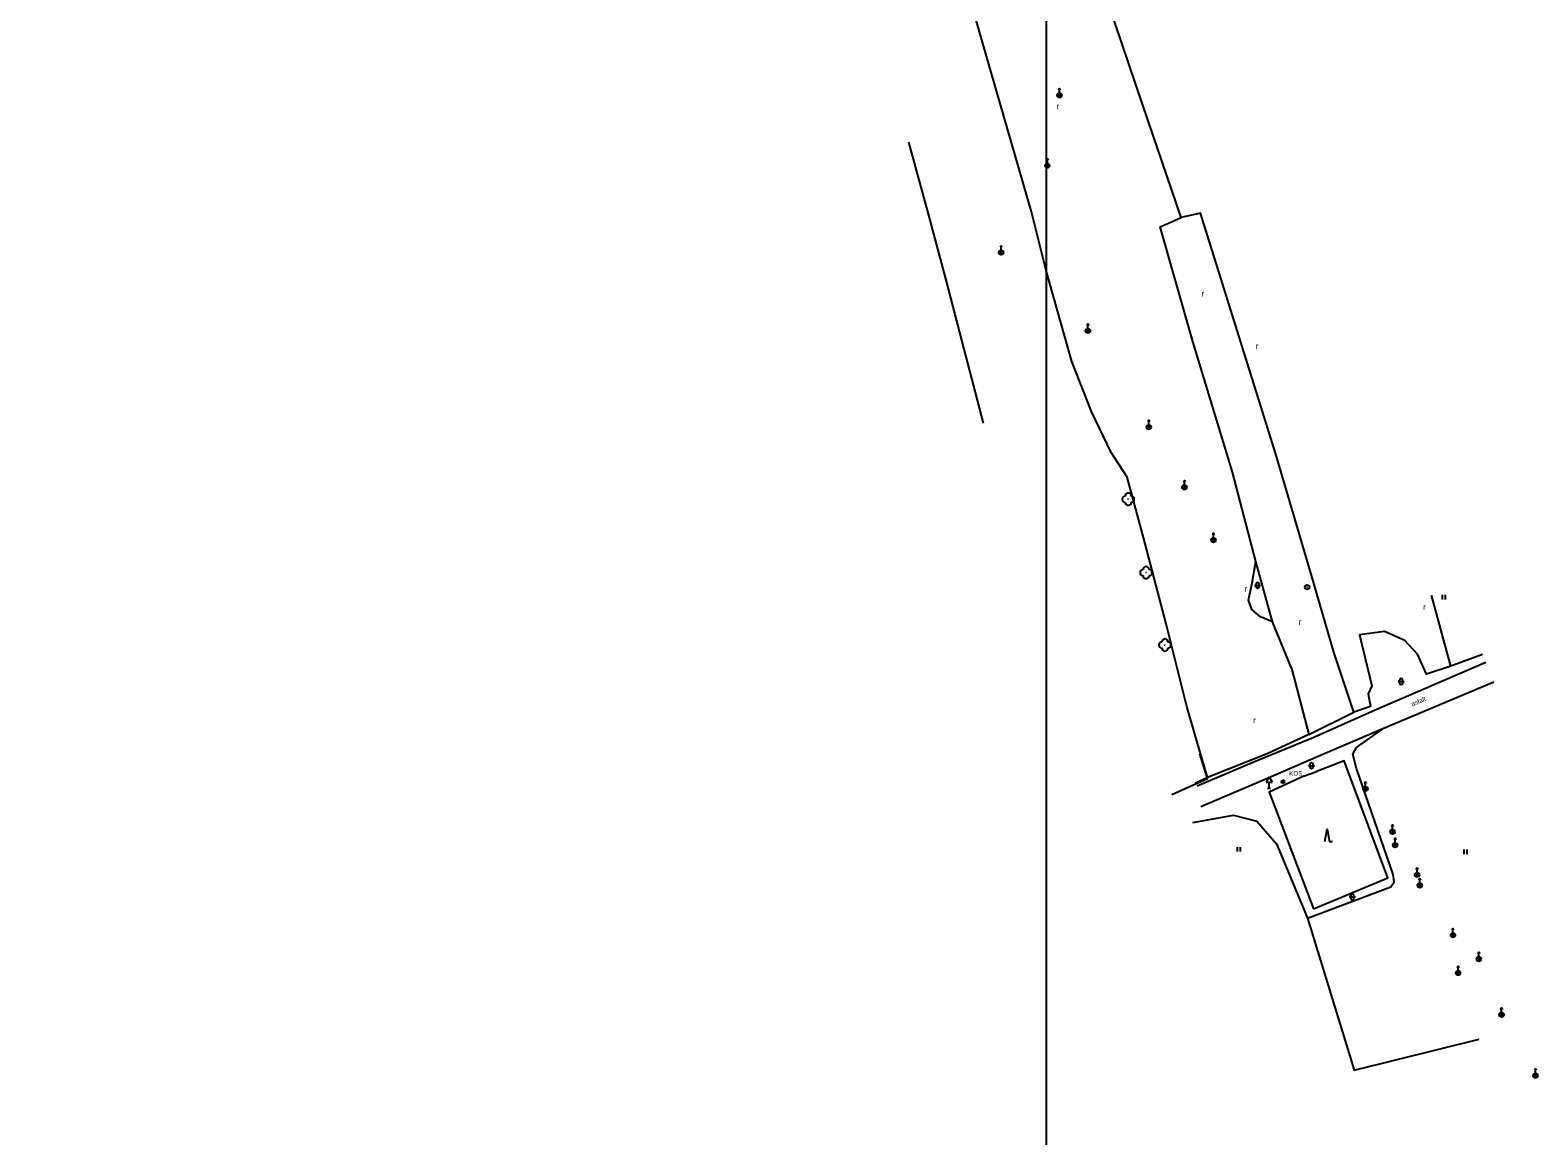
# Model space of a CAD drawing. Extents: x -582188 to -561562, y -1187250 to -1183500.
# Drawn here: x -575479.1 to -575231.9, y -1183947 to -1183765.7 of the extents above; entities that cross this region are included whole.
import ezdxf

# ---------------------------------------------------------------- set-up
doc = ezdxf.new("R2010")
doc.units = 0
for name, color, linetype in [('MAP_ZN_BP', 7, 'Continuous'), ('POMOC_POPIS', 7, 'Continuous'), ('ROZHRANÍ_PLOCH', 7, 'Continuous'), ('RÁMY_ML', 7, 'Continuous'), ('ZELEŇ', 7, 'Continuous'), ('ZN_BP', 7, 'Continuous'), ('ZN_DOPLŇKOVÉ', 7, 'Continuous'), ('ZN_KULTUR', 7, 'Continuous')]:
    doc.layers.add(name, color=color, linetype=linetype)

msp = doc.modelspace()

# ---------------------------------------------------------------- linework, layer by layer
at = {"layer": 'MAP_ZN_BP'}
for radius in [0.375, 0.0005]:
    msp.add_circle((-575269.75, -1183856.991), radius, dxfattribs=at)
at = {"layer": 'ROZHRANÍ_PLOCH'}
for points in [[(-575240.45, -1183869.34), (-575258.62, -1183877.16), (-575268.65, -1183881.64), (-575278.76, -1183885.82), (-575287.77, -1183889.63)], [(-575239.12, -1183872.56), (-575257.33, -1183880.22), (-575267.93, -1183884.77), (-575276.92, -1183888.62), (-575287.2, -1183893.03)]]:
    msp.add_lwpolyline(points, dxfattribs=at)
at = {"layer": 'RÁMY_ML'}
msp.add_lwpolyline([(-575625, -1184000), (-575312.5, -1184000), (-575312.5, -1183750)], dxfattribs=at)
at = {"layer": 'ZELEŇ'}
for p, q in [((-575269.48, -1183881.13), (-575262.11, -1183877.47)), ((-575286.07, -1183888.19), (-575288.09, -1183889.16))]:
    msp.add_line(p, q, dxfattribs=at)
for points in [[(-575272.31, -1183870.28), (-575275.45, -1183862.67), (-575278.15, -1183852.81), (-575281.97, -1183838.13), (-575288.5, -1183816.7), (-575293.86, -1183797.92), (-575290.42, -1183796.4), (-575296.7, -1183777.96), (-575301.3, -1183764.43), (-575306.69, -1183747.6), (-575310.14, -1183736.48), (-575316.18, -1183717.89), (-575322.17, -1183699.18), (-575332.15, -1183671.46)], [(-575272.31, -1183870.28), (-575269.48, -1183881.13), (-575276.3, -1183884.31), (-575286.07, -1183888.19), (-575289.47, -1183876.56), (-575292.87, -1183862.99), (-575296.61, -1183848.85), (-575299.24, -1183838.98), (-575301.89, -1183834.9), (-575305.14, -1183828.2), (-575308.34, -1183820), (-575312.52, -1183805.06), (-575314.93, -1183795.43), (-575320.82, -1183775.21), (-575324.61, -1183761.94), (-575327.94, -1183750.31), (-575319.54, -1183748.15), (-575321.88, -1183739.85), (-575337.2, -1183686.33)], [(-575322.8, -1183830.13), (-575326.4, -1183816.52), (-575328.86, -1183807.03), (-575331.76, -1183796.03), (-575335.07, -1183784.01)], [(-575241, -1183868.05), (-575246.17, -1183869.97), (-575250.2, -1183871.26), (-575251.68, -1183867.97), (-575253.76, -1183865.76), (-575257.08, -1183864.29), (-575261.16, -1183864.83), (-575259.14, -1183873.17), (-575259.76, -1183874.5), (-575259.37, -1183876.55), (-575262.11, -1183877.47), (-575265.36, -1183867.65), (-575269.11, -1183854.88), (-575274.88, -1183835.2), (-575287.26, -1183795.66), (-575290.42, -1183796.4)], [(-575275.45, -1183862.67), (-575277.4, -1183861.88), (-575278.83, -1183860.68), (-575279.36, -1183859.1), (-575278.78, -1183856.28), (-575278.15, -1183852.81)], [(-575246.17, -1183869.97), (-575249.36, -1183858.32)], [(-575261.66, -1183883.28), (-575257.33, -1183880.22)], [(-575291.96, -1183891), (-575286.1, -1183888.34), (-575287.34, -1183884.34)], [(-575269.7, -1183911.24), (-575256.04, -1183906.13), (-575255.49, -1183905.31), (-575255.67, -1183904.1), (-575261.64, -1183886.71), (-575262.27, -1183884.39), (-575261.66, -1183883.28)], [(-575288.49, -1183895.57), (-575281.85, -1183894.35), (-575278.01, -1183895.36), (-575274.79, -1183899.07), (-575269.7, -1183911.24), (-575262.04, -1183936.16), (-575241.55, -1183931.08)]]:
    msp.add_lwpolyline(points, dxfattribs=at)
for centre in [(-575299.09, -1183842.57), (-575296.16, -1183854.6), (-575293.08, -1183866.49)]:
    msp.add_circle(centre, 0.0005, dxfattribs=at)
for centre, start, end in [((-575299.59, -1183842.57), 89.99999, 269.99999), ((-575299.09, -1183842.07), 0, 179.99999), ((-575298.59, -1183842.57), 270, 89.99999), ((-575299.09, -1183843.07), 179.99999, 359.99999), ((-575296.66, -1183854.6), 89.99999, 269.99999), ((-575296.16, -1183854.1), 0, 179.99999), ((-575295.66, -1183854.6), 270, 89.99999), ((-575296.16, -1183855.1), 179.99999, 359.99999), ((-575293.58, -1183866.49), 89.99999, 269.99999), ((-575293.08, -1183865.99), 0, 179.99999), ((-575293.08, -1183866.99), 179.99999, 359.99999), ((-575292.58, -1183866.49), 270, 89.99999)]:
    msp.add_arc(centre, 0.5, start, end, dxfattribs=at)
at = {"layer": 'ZN_BP'}
for p, q in [((-575310.37, -1183775.985), (-575310.37, -1183775.235)), ((-575310.635, -1183776.624), (-575310.106, -1183776.096)), ((-575310.106, -1183776.628), (-575310.635, -1183776.096)), ((-575312.615, -1183788.144), (-575312.086, -1183787.616)), ((-575312.086, -1183788.148), (-575312.615, -1183787.616)), ((-575312.35, -1183787.505), (-575312.35, -1183786.755)), ((-575320.195, -1183802.394), (-575319.666, -1183801.866)), ((-575319.666, -1183802.398), (-575320.195, -1183801.866)), ((-575319.93, -1183801.755), (-575319.93, -1183801.005)), ((-575305.965, -1183815.224), (-575305.436, -1183814.696)), ((-575305.436, -1183815.228), (-575305.965, -1183814.696)), ((-575305.7, -1183814.585), (-575305.7, -1183813.835)), ((-575295.71, -1183830.385), (-575295.71, -1183829.635)), ((-575295.975, -1183831.024), (-575295.446, -1183830.496)), ((-575295.446, -1183831.028), (-575295.975, -1183830.496)), ((-575289.88, -1183840.235), (-575289.88, -1183839.485)), ((-575290.145, -1183840.874), (-575289.616, -1183840.346)), ((-575289.616, -1183840.878), (-575290.145, -1183840.346)), ((-575285.375, -1183849.534), (-575284.846, -1183849.006)), ((-575284.846, -1183849.538), (-575285.375, -1183849.006)), ((-575285.11, -1183848.895), (-575285.11, -1183848.145)), ((-575260.2, -1183889.675), (-575260.2, -1183888.925)), ((-575260.465, -1183890.314), (-575259.936, -1183889.786)), ((-575259.936, -1183890.318), (-575260.465, -1183889.786)), ((-575256.025, -1183897.354), (-575255.496, -1183896.826)), ((-575255.496, -1183897.358), (-575256.025, -1183896.826)), ((-575255.76, -1183896.715), (-575255.76, -1183895.965)), ((-575255.595, -1183899.554), (-575255.066, -1183899.026)), ((-575255.066, -1183899.558), (-575255.595, -1183899.026)), ((-575255.33, -1183898.915), (-575255.33, -1183898.165)), ((-575251.995, -1183904.414), (-575251.466, -1183903.886)), ((-575251.466, -1183904.418), (-575251.995, -1183903.886)), ((-575251.73, -1183903.775), (-575251.73, -1183903.025)), ((-575251.545, -1183906.154), (-575251.016, -1183905.626)), ((-575251.016, -1183906.158), (-575251.545, -1183905.626)), ((-575251.28, -1183905.515), (-575251.28, -1183904.765)), ((-575246.105, -1183914.324), (-575245.576, -1183913.796)), ((-575245.576, -1183914.328), (-575246.105, -1183913.796)), ((-575245.84, -1183913.685), (-575245.84, -1183912.935)), ((-575245, -1183919.885), (-575245, -1183919.135)), ((-575241.875, -1183918.234), (-575241.346, -1183917.706)), ((-575241.346, -1183918.238), (-575241.875, -1183917.706)), ((-575241.61, -1183917.595), (-575241.61, -1183916.845)), ((-575245.265, -1183920.524), (-575244.736, -1183919.996)), ((-575244.736, -1183920.528), (-575245.265, -1183919.996)), ((-575237.87, -1183926.725), (-575237.87, -1183925.975)), ((-575238.135, -1183927.364), (-575237.606, -1183926.836)), ((-575237.606, -1183927.368), (-575238.135, -1183926.836)), ((-575232.3, -1183936.695), (-575232.3, -1183935.945)), ((-575232.565, -1183937.334), (-575232.036, -1183936.806)), ((-575232.036, -1183937.338), (-575232.565, -1183936.806))]:
    msp.add_line(p, q, dxfattribs=at)
for points in [[(-575310.495, -1183775.485), (-575310.37, -1183775.235), (-575310.245, -1183775.485)], [(-575312.475, -1183787.005), (-575312.35, -1183786.755), (-575312.225, -1183787.005)], [(-575320.055, -1183801.255), (-575319.93, -1183801.005), (-575319.805, -1183801.255)], [(-575305.825, -1183814.085), (-575305.7, -1183813.835), (-575305.575, -1183814.085)], [(-575295.835, -1183829.885), (-575295.71, -1183829.635), (-575295.585, -1183829.885)], [(-575290.005, -1183839.735), (-575289.88, -1183839.485), (-575289.755, -1183839.735)], [(-575285.235, -1183848.395), (-575285.11, -1183848.145), (-575284.985, -1183848.395)], [(-575260.325, -1183889.175), (-575260.2, -1183888.925), (-575260.075, -1183889.175)], [(-575255.885, -1183896.215), (-575255.76, -1183895.965), (-575255.635, -1183896.215)], [(-575255.455, -1183898.415), (-575255.33, -1183898.165), (-575255.205, -1183898.415)], [(-575251.855, -1183903.275), (-575251.73, -1183903.025), (-575251.605, -1183903.275)], [(-575251.405, -1183905.015), (-575251.28, -1183904.765), (-575251.155, -1183905.015)], [(-575245.965, -1183913.185), (-575245.84, -1183912.935), (-575245.715, -1183913.185)], [(-575245.125, -1183919.385), (-575245, -1183919.135), (-575244.875, -1183919.385)], [(-575241.735, -1183917.095), (-575241.61, -1183916.845), (-575241.485, -1183917.095)], [(-575237.995, -1183926.225), (-575237.87, -1183925.975), (-575237.745, -1183926.225)], [(-575232.425, -1183936.195), (-575232.3, -1183935.945), (-575232.175, -1183936.195)]]:
    msp.add_lwpolyline(points, dxfattribs=at)
for centre in [(-575310.37, -1183776.36), (-575312.35, -1183787.88), (-575319.93, -1183802.13), (-575305.7, -1183814.96), (-575295.71, -1183830.76), (-575289.88, -1183840.61), (-575285.11, -1183849.27), (-575260.2, -1183890.05), (-575255.76, -1183897.09), (-575255.33, -1183899.29), (-575251.73, -1183904.15), (-575251.28, -1183905.89), (-575245.84, -1183914.06), (-575241.61, -1183917.97), (-575245, -1183920.26), (-575237.87, -1183927.1), (-575232.3, -1183937.07)]:
    msp.add_circle(centre, 0.375, dxfattribs=at)
at = {"layer": 'ZN_DOPLŇKOVÉ'}
for p, q in [((-575276, -1183888.074), (-575276.5, -1183888.94)), ((-575276.5, -1183888.94), (-575275.5, -1183888.94)), ((-575276, -1183888.074), (-575275.5, -1183888.94)), ((-575276, -1183889.94), (-575276, -1183888.94)), ((-575276.25, -1183889.94), (-575275.75, -1183889.94))]:
    msp.add_line(p, q, dxfattribs=at)
for points in [[(-575268.69, -1183909.74), (-575256.55, -1183904.67), (-575263.7, -1183885.48), (-575268.31, -1183887.28)], [(-575270.17, -1183887.93), (-575276, -1183890.58), (-575268.69, -1183909.74)], [(-575270.17, -1183887.93), (-575268.31, -1183887.28)]]:
    msp.add_lwpolyline(points, dxfattribs=at)
for radius in [0.25, 0.0005]:
    msp.add_circle((-575273.711, -1183888.9), radius, dxfattribs=at)
at = {"layer": 'ZN_KULTUR'}
for p, q in [((-575278.39, -1183856.7), (-575277.39, -1183856.7)), ((-575278.14, -1183856.95), (-575278.14, -1183856.45)), ((-575277.64, -1183856.95), (-575277.64, -1183856.45)), ((-575247.58, -1183858.995), (-575247.58, -1183858.245)), ((-575247.08, -1183858.995), (-575247.08, -1183858.245)), ((-575254.59, -1183872.72), (-575254.59, -1183872.22)), ((-575254.09, -1183872.72), (-575254.09, -1183872.22)), ((-575254.84, -1183872.47), (-575253.84, -1183872.47)), ((-575269.54, -1183886.26), (-575268.54, -1183886.26)), ((-575269.29, -1183886.51), (-575269.29, -1183886.01)), ((-575268.79, -1183886.51), (-575268.79, -1183886.01)), ((-575281.18, -1183900.355), (-575281.18, -1183899.605)), ((-575280.68, -1183900.355), (-575280.68, -1183899.605)), ((-575244, -1183900.755), (-575244, -1183900.005)), ((-575243.5, -1183900.755), (-575243.5, -1183900.005)), ((-575262.85, -1183907.76), (-575261.85, -1183907.76)), ((-575262.6, -1183908.01), (-575262.6, -1183907.51)), ((-575262.1, -1183908.01), (-575262.1, -1183907.51))]:
    msp.add_line(p, q, dxfattribs=at)
msp.add_lwpolyline([(-575266.855, -1183898.67), (-575266.48, -1183896.67), (-575266.105, -1183898.67), (-575265.605, -1183898.67)], dxfattribs=at)
for centre, start, end in [((-575277.89, -1183856.45), 0, 179.99999), ((-575277.89, -1183856.95), 179.99999, 359.99999), ((-575254.34, -1183872.22), 0, 179.99999), ((-575254.34, -1183872.72), 179.99999, 359.99999), ((-575269.04, -1183886.01), 0, 179.99999), ((-575269.04, -1183886.51), 179.99999, 359.99999), ((-575262.35, -1183907.51), 0, 179.99999), ((-575262.35, -1183908.01), 179.99999, 359.99999)]:
    msp.add_arc(centre, 0.25, start, end, dxfattribs=at)

# ---------------------------------------------------------------- texts
at = {"layer": 'POMOC_POPIS'}
msp.add_text('asfalt', height=0.75, rotation=22.81396, dxfattribs=at).set_placement((-575252.5, -1183876.56))
msp.add_text('KOS', height=0.75, dxfattribs=at).set_placement((-575272.71, -1183887.9))
at = {"layer": 'ZN_KULTUR'}
for p in [(-575310.858, -1183778.662), (-575287.088, -1183809.342), (-575278.168, -1183817.952), (-575280.048, -1183857.762), (-575271.128, -1183863.182), (-575250.728, -1183860.732), (-575278.638, -1183879.302)]:
    msp.add_text('r', height=1, dxfattribs=at).set_placement(p)

doc.saveas('drawing.dxf')
